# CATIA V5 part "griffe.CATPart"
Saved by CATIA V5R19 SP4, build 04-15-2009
Part number: griffe
Bounding box of the stored display mesh (mm): x 0 to 7, y -25.933 to 6.35, z -7.312 to 100
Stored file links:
  E:\IAO_2010\iao\IAO_MMS_Groupe1\Problemes\tlampure\tlampure\tlampure\griffe.CATPart
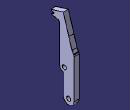
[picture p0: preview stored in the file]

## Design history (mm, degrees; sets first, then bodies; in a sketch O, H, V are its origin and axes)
Body1 (main body)
  Sketch1 on yz-plane, origin (0, 0, 0), H (0, 1, 0), V (0, 0, 1)
  Sketch2 on yz-plane, origin (0, 0, 0), H (0, 1, 0), V (0, 0, 1)
    point P1 (6.3496, 55)
    line L1 (6.3496, 54.0382) -> (6.3496, 0)
    point P2 (6.3496, 0)
    point P3 (0, -7.4112)
    point P4 (-8.6504, 0)
    line L2 (5.7591, 55.7592) -> (5.3472, 56.2888)
    line L3 (3.4149, 60.0271) -> (-0.9837, 74.5997)
    arc A1 centre (3.5462, 54.0382) radius 2.8034 from (6.3496, 54.0382) to (5.7591, 55.7592) ccw
    arc A2 centre (14.428, 63.3513) radius 11.5039 from (5.3472, 56.2888) to (3.4149, 60.0271) cw
    line L4 (-0.9837, 74.5997) -> (-8.6504, 100)
    point P13 (-8.6504, 100)
    line L5 (-8.6504, 100) -> (-25.9333, 94.7834)
    line L6 (-25.9333, 94.7834) -> (-21.0033, 92.4934)
    line L7 (-21.0033, 92.4934) -> (-25.4356, 89.5312)
    line L8 (-25.4356, 89.5312) -> (-16.2503, 87.6988)
    line L9 (-14.0631, 85.0322) -> (-14.0631, 34.6638)
    arc A3 centre (-7.2547, 34.6638) radius 6.8084 from (-14.0631, 34.6638) to (-8.6504, 28) ccw
    circle A4 centre (-7.2547, 34.6638) radius 3
    arc A5 centre (-16.7822, 85.0322) radius 2.7191 from (-14.0631, 85.0322) to (-16.2503, 87.6988) ccw
    line L10 (-8.6504, 28) -> (-8.6504, 0)
    arc A6 centre (-1.1504, 0) radius 7.5 from (-8.6504, 0) to (6.3496, 0) ccw
    circle A7 centre (-1.1504, 0) radius 3
    point P23 (-1.1504, 0)
    distance P1 P2 = 55
    radius A1 = 2.8034
    radius A2 = 11.5039
    distance P4 P13 = 100
    radius A5 = 2.7191
    length L10 = 28
    coincidence: P2 H, P3 V, P4 H, L1 P1, L2 P1, P23 H
    vertical: L1 V, L9 V, L10 V
    tangency: A1 L1, A1 L2, A2 L2, A2 L3, L4 A2, L6 A2, A3 L9, A5 L9, A5 L8, A6 L1, A6 L10
    perpendicularity: L5 L3
    concentricity: A6 A7
  Pad1: profile Sketch2, direction (1, 0, 0), length 7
